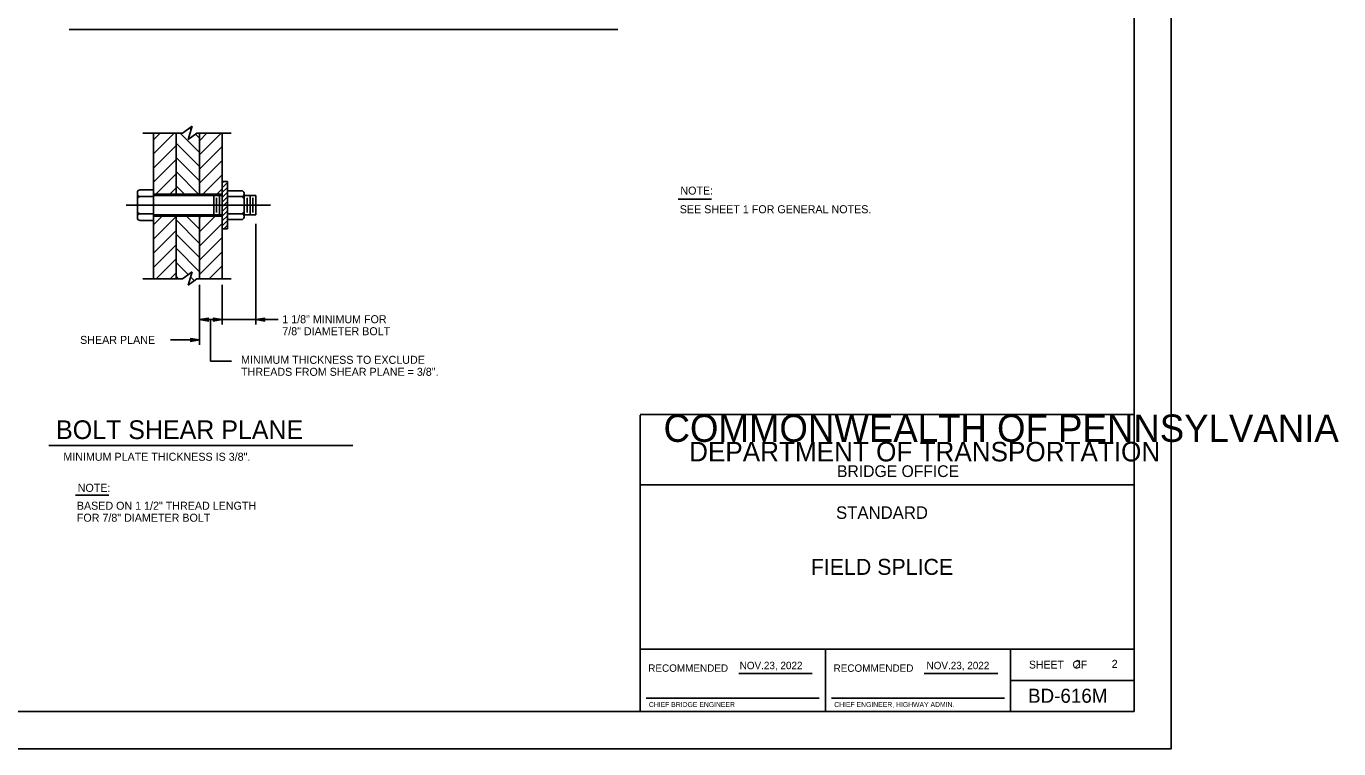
# Model space of a CAD drawing. Extents: x 638466 to 639375, y 297808 to 298996.
# Drawn here: x 638844 to 639375, y 297808 to 298101 of the extents above; entities that cross this region are included whole.
import ezdxf

# ---------------------------------------------------------------- set-up
doc = ezdxf.new("R2010")
doc.units = 0
for name, color, linetype in [('1', 7, 'Continuous'), ('2', 7, 'Continuous'), ('4', 7, 'Continuous'), ('PLT-BNDY', 7, 'Continuous'), ('SIGNATORY TITLES', 7, 'Continuous')]:
    doc.layers.add(name, color=color, linetype=linetype)

msp = doc.modelspace()

# ---------------------------------------------------------------- linework, layer by layer
at = {"layer": '1'}
for p, q in [((639291.96, 297823.46), (639291.96, 298387.46)), ((638924.98, 298037.96), (638922.83, 298037.96)), ((638922.84, 298037.25), (638923.55, 298037.96)), ((638922.84, 298037.95), (638922.84, 298018.79)), ((638922.84, 298035.34), (638924.98, 298037.48)), ((638924.98, 298037.96), (638924.98, 298018.8)), ((638888.56, 298023.16), (638888.56, 298033.6)), ((638895.02, 298034.54), (638889.64, 298034.54)), ((638889.64, 298031.83), (638895.03, 298031.83)), ((638894.92, 298032.29), (638922.73, 298032.29)), ((638895.02, 298022.21), (638895.02, 298034.54)), ((638919.46, 298032.29), (638919.46, 298024.46)), ((638920.61, 298031.35), (638920.61, 298025.38)), ((638921.72, 298032.29), (638921.72, 298024.46)), ((638922.84, 298033.43), (638924.98, 298035.57)), ((638922.84, 298031.52), (638924.98, 298033.66)), ((638922.84, 298029.61), (638924.98, 298031.75)), ((638930.64, 298034.19), (638924.98, 298034.19)), ((638930.64, 298031.83), (638924.98, 298031.83)), ((638931.71, 298033.24), (638931.71, 298023.51)), ((638936.5, 298032.3), (638931.71, 298032.3)), ((638932.94, 298031.36), (638932.94, 298025.39)), ((638934.17, 298032.3), (638934.17, 298024.45)), ((638935.33, 298031.36), (638935.33, 298025.39)), ((638936.5, 298032.3), (638936.5, 298024.45)), ((638884, 298028.37), (638942.46, 298028.37)), ((638922.84, 298027.7), (638924.98, 298029.84)), ((638922.84, 298025.79), (638924.98, 298027.93)), ((638922.84, 298023.89), (638924.98, 298026.03)), ((639107.41, 298030.8), (639120.88, 298030.8)), ((638895.02, 298022.21), (638889.59, 298022.21)), ((638889.64, 298024.92), (638895.03, 298024.92)), ((638894.92, 298024.46), (638922.73, 298024.46)), ((638922.84, 298021.98), (638924.98, 298024.12)), ((638922.84, 298020.07), (638924.98, 298022.21)), ((638930.64, 298024.92), (638924.98, 298024.92)), ((638930.64, 298022.56), (638924.98, 298022.56)), ((638936.5, 298024.45), (638931.71, 298024.45)), ((638924.98, 298018.8), (638922.83, 298018.8)), ((638923.48, 298018.8), (638924.98, 298020.3)), ((639091.96, 297943.68), (639291.96, 297943.68)), ((639091.96, 297943.46), (639091.96, 297823.46)), ((639091.96, 297943.46), (639091.96, 297823.46)), ((639091.96, 297915.21), (639291.96, 297915.21)), ((638863.55, 297911.05), (638877.02, 297911.05)), ((639091.96, 297848.76), (639291.96, 297848.76)), ((639166.96, 297823.46), (639166.96, 297848.46)), ((639241.96, 297848.46), (639241.96, 297823.46)), ((639241.96, 297848.46), (639241.96, 297823.46)), ((639241.96, 297836.1), (639291.96, 297836.1)), ((639247.66, 297836.1), (639291.96, 297836.1)), ((639094.46, 297828.96), (639164.46, 297828.96)), ((639169.46, 297828.96), (639239.46, 297828.96)), ((638505.96, 297823.46), (639291.96, 297823.46))]:
    msp.add_line(p, q, dxfattribs=at)
for points in [[(638917.09, 297981.63), (638916.97, 297981.88), (638913.66, 297982.07), (638917.09, 297981.63), (638917.27, 297981.48), (638913.66, 297982.07), (638916.96, 297982.23), (638917.08, 297982.48), (638913.66, 297982.07), (638917.27, 297982.64), (638917.08, 297982.48)], [(638919.41, 297981.63), (638919.53, 297981.88), (638922.84, 297982.07), (638919.41, 297981.63), (638919.23, 297981.48), (638922.84, 297982.07), (638919.54, 297982.23), (638919.42, 297982.48), (638922.84, 297982.07), (638919.23, 297982.64), (638919.42, 297982.48)], [(638939.93, 297981.63), (638939.81, 297981.88), (638936.5, 297982.07), (638939.93, 297981.63), (638940.11, 297981.48), (638936.5, 297982.07), (638939.8, 297982.23), (638939.92, 297982.48), (638936.5, 297982.07), (638940.11, 297982.64), (638939.92, 297982.48)], [(638910.23, 297973.4), (638910.35, 297973.65), (638913.66, 297973.84), (638910.23, 297973.4), (638910.05, 297973.25), (638913.66, 297973.84), (638910.36, 297974), (638910.24, 297974.24), (638913.66, 297973.84), (638910.05, 297974.41), (638910.24, 297974.24)]]:
    msp.add_lwpolyline(points, dxfattribs=at)
for centre, major_axis, start_param, end_param in [((638889.64, 298033.6), (1.08, 0), 1.570796, 3.141593), ((638889.64, 298032.77), (-1.08, 0), 0, 1.570796), ((638889.64, 298030.89), (1.08, 0), 1.570796, 3.141593), ((638930.64, 298033.24), (1.08, 0), 0, 1.570796), ((638930.64, 298032.77), (-1.08, 0), 1.570796, 3.141593), ((638930.64, 298030.89), (1.08, 0), 0, 1.570796), ((638889.64, 298025.86), (-1.08, 0), 0, 1.570796), ((638930.64, 298025.86), (-1.08, 0), 1.570796, 3.141593), ((638889.64, 298023.98), (1.08, 0), 1.570796, 3.141593), ((638889.64, 298023.16), (-1.08, 0), 0, 1.570796), ((638930.64, 298023.98), (1.08, 0), 0, 1.570796), ((638930.64, 298023.51), (-1.08, 0), 1.570796, 3.141593)]:
    msp.add_ellipse(centre, major_axis=major_axis, ratio=0.875, start_param=start_param, end_param=end_param, dxfattribs=at)
at = {"layer": '2'}
for p, q in [((638910.74, 298060.3), (638906.75, 298057.47)), ((638909.03, 298054.91), (638910.74, 298060.3)), ((638909.59, 298059.49), (638910.27, 298058.81)), ((638895.03, 297998.58), (638895.03, 298057.47)), ((638895.03, 298054.79), (638897.71, 298057.47)), ((638895.03, 298049.07), (638903.43, 298057.47)), ((638895.03, 298043.34), (638904.21, 298052.52)), ((638904.21, 298032.83), (638904.21, 298057.47)), ((638904.21, 298053.41), (638913.66, 298043.96)), ((638905.89, 298057.47), (638913.66, 298049.69)), ((638912.62, 298057.46), (638909.03, 298054.91)), ((638912.04, 298057.05), (638913.66, 298055.42)), ((638913.66, 298032.83), (638913.66, 298057.47)), ((638913.66, 298054.42), (638916.71, 298057.47)), ((638913.66, 298048.69), (638922.44, 298057.47)), ((638922.84, 297998.58), (638922.84, 298057.47)), ((638904.21, 298047.69), (638913.66, 298038.24)), ((638913.66, 298042.97), (638922.84, 298052.15)), ((638895.03, 298037.61), (638904.21, 298046.79)), ((638904.21, 298041.96), (638913.34, 298032.83)), ((638913.66, 298037.24), (638922.84, 298046.42)), ((638895.98, 298032.83), (638904.21, 298041.06)), ((638914.98, 298032.83), (638922.84, 298040.69)), ((638895.03, 298032.83), (638922.84, 298032.83)), ((638901.71, 298032.83), (638904.21, 298035.34)), ((638904.21, 298036.23), (638907.61, 298032.83)), ((638920.71, 298032.83), (638922.84, 298034.96)), ((638895.03, 298023.92), (638922.84, 298023.92)), ((638895.03, 298020.39), (638898.57, 298023.92)), ((638895.03, 298014.66), (638904.21, 298023.84)), ((638904.21, 297998.58), (638904.21, 298023.92)), ((638904.21, 298022.37), (638913.66, 298012.92)), ((638908.39, 298023.92), (638913.66, 298018.65)), ((638913.66, 297998.58), (638913.66, 298023.92)), ((638913.66, 298023.25), (638914.34, 298023.92)), ((638913.66, 298017.52), (638920.07, 298023.92)), ((638913.66, 298011.79), (638922.84, 298020.97)), ((638895.03, 298008.93), (638904.21, 298018.11)), ((638904.21, 298016.64), (638913.66, 298007.19)), ((638913.66, 298006.06), (638922.84, 298015.24)), ((638895.03, 298003.2), (638904.21, 298012.38)), ((638904.21, 298010.91), (638913.66, 298001.46)), ((638896.14, 297998.58), (638904.21, 298006.65)), ((638904.21, 298005.19), (638909.13, 298000.27)), ((638913.66, 298000.33), (638922.84, 298009.51)), ((638901.86, 297998.58), (638904.21, 298000.93)), ((638904.21, 297999.46), (638905.09, 297998.58)), ((638910.08, 297999.32), (638911.57, 297997.83)), ((638917.63, 297998.58), (638922.84, 298003.79)), ((639131.92, 297838.96), (639161.69, 297838.96)), ((639206.92, 297838.96), (639236.83, 297838.96))]:
    msp.add_line(p, q, dxfattribs=at)
at = {"layer": '4'}
for p, q in [((639082.94, 298099.38), (638860.88, 298099.38)), ((638890.72, 298057.47), (638906.75, 298057.47)), ((638912.63, 298057.47), (638926.52, 298057.47)), ((638936.5, 297980.04), (638936.5, 298020.75)), ((638910.74, 298001.41), (638906.75, 297998.58)), ((638909.03, 297996.02), (638910.74, 298001.41)), ((638890.72, 297998.58), (638906.75, 297998.58)), ((638912.62, 297998.57), (638909.03, 297996.02)), ((638912.63, 297998.58), (638926.52, 297998.58)), ((638913.66, 297971.89), (638913.66, 297996.15)), ((638922.84, 297980.04), (638922.84, 297996.12)), ((638945.48, 297982.07), (638913.66, 297982.07)), ((638918.19, 297965.3), (638918.19, 297982.07)), ((638901.88, 297973.84), (638913.66, 297973.84)), ((638918.19, 297965.3), (638926.57, 297965.3)), ((638975.68, 297931.2), (638852.65, 297931.2))]:
    msp.add_line(p, q, dxfattribs=at)
at = {"layer": 'PLT-BNDY'}
msp.add_lwpolyline([(638465.96, 298402.46), (639306.96, 298402.46), (639306.96, 297808.46), (638465.96, 297808.46)], close=True, dxfattribs=at)

# ---------------------------------------------------------------- texts
at = {"layer": '1'}
for s, height, p in [('COMMONWEALTH OF PENNSYLVANIA', 11.0789, (639101.48, 297932.6)), ('COMMONWEALTH OF PENNSYLVANIA', 11.0789, (639101.48, 297932.6)), ('DEPARTMENT OF TRANSPORTATION', 7.8962, (639111.83, 297924.71)), ('DEPARTMENT OF TRANSPORTATION', 7.8962, (639111.83, 297924.71)), ('BRIDGE OFFICE', 4.7495, (639171.68, 297918.38)), ('NOTE:', 3.24, (638864.39, 297912.39)), ('STANDARD', 5.055, (639171.3, 297901.46)), ('FIELD SPLICE', 6.4602, (639161.07, 297878.81)), ('RECOMMENDED', 3, (639095.29, 297839.58)), ('RECOMMENDED', 3, (639170.29, 297839.58)), ('SHEET   OF', 3.166, (639249.38, 297840.9)), ('2', 3.29, (639267.92, 297841.09)), ('2', 3.29, (639282.83, 297841.13)), ('BD-616M', 5.687, (639249, 297827.06))]:
    msp.add_text(s, height=height, dxfattribs=at).set_placement(p)
at = {"layer": '4'}
for s, height, p in [('NOTE:', 3.24, (639108.3, 298032.64)), ('SEE SHEET 1 FOR GENERAL NOTES.', 3.24, (639108.06, 298025.1)), ('1 1/8" MINIMUM FOR', 3.24, (638947.18, 297980.61)), ('7/8" DIAMETER BOLT', 3.24, (638947.18, 297975.75)), ('SHEAR PLANE', 3.24, (638865.37, 297972.24)), ('MINIMUM THICKNESS TO EXCLUDE', 3.24, (638930.5, 297964.18)), ('THREADS FROM SHEAR PLANE = 3/8".', 3.24, (638930.5, 297959.33)), ('BOLT SHEAR PLANE', 7.56, (638855.64, 297933.75)), ('MINIMUM PLATE THICKNESS IS 3/8".', 3.24, (638858.58, 297924.96)), ('BASED ON 1 1/2" THREAD LENGTH', 3.24, (638864.04, 297905.15)), ('FOR 7/8" DIAMETER BOLT', 3.24, (638864.04, 297900.3))]:
    msp.add_text(s, height=height, dxfattribs=at).set_placement(p)
at = {"layer": 'SIGNATORY TITLES'}
for s, height, p in [('NOV.23, 2022', 3, (639132.29, 297840.64)), ('NOV.23, 2022', 3, (639207.91, 297840.64)), ('CHIEF BRIDGE ENGINEER', 2, (639095.55, 297825.33)), ('CHIEF ENGINEER, HIGHWAY ADMIN.', 2, (639170.55, 297825.33))]:
    msp.add_text(s, height=height, dxfattribs=at).set_placement(p)

doc.saveas('drawing.dxf')
